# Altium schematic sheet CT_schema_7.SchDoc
size 251 x 159 mm
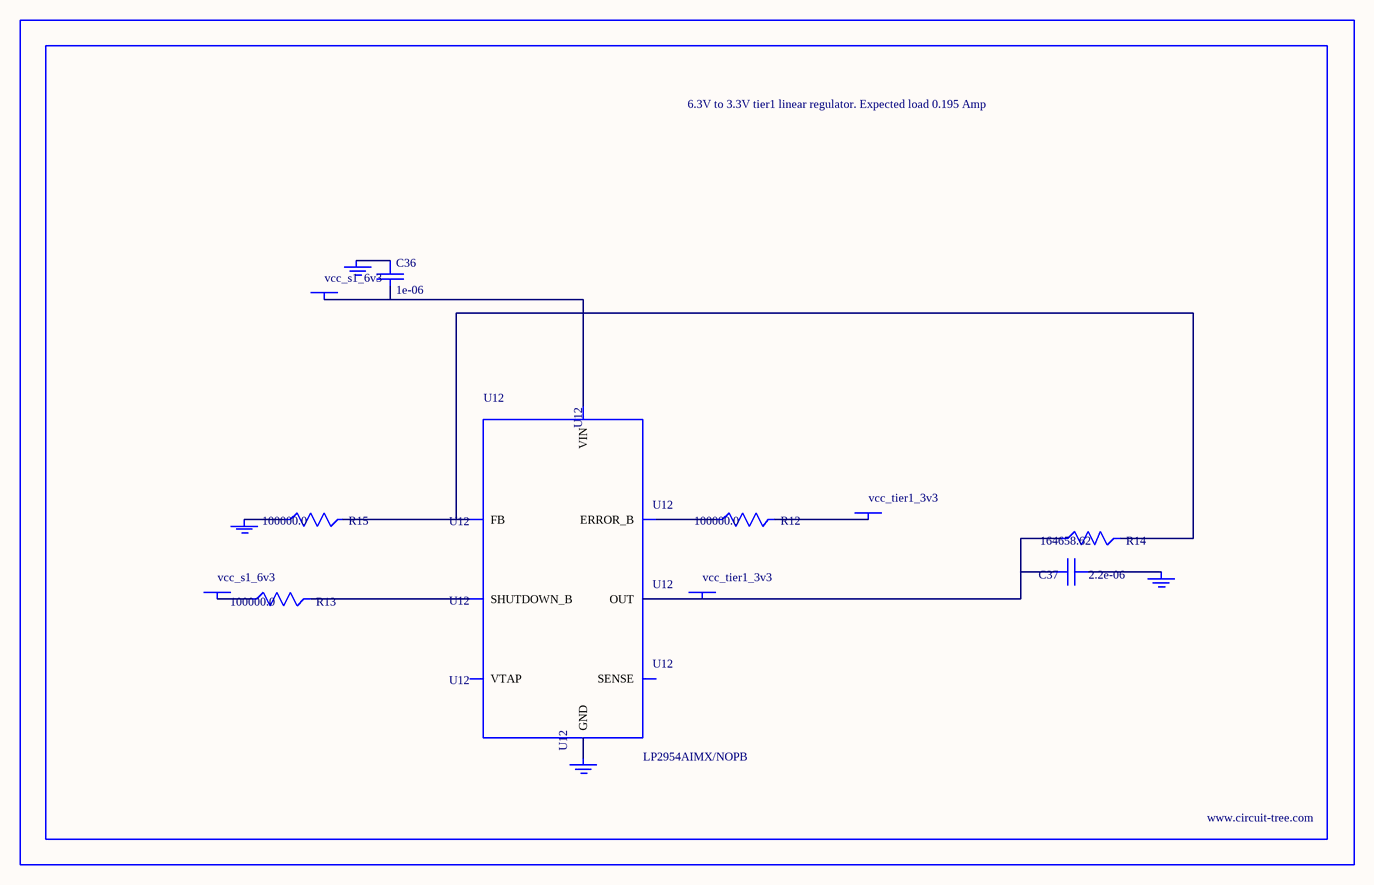
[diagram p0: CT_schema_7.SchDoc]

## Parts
BORDER6  (no value)
C36  1e-06  [EXV-9B]
C37  2.2e-06  [EXV-9B]
GND_INSTANCE_6_0  (no value)
GND_INSTANCE_6_1  (no value)
GND_INSTANCE_6_2  (no value)
GND_INSTANCE_6_3  (no value)
POWER_INSTANCE_6_0  vcc_s1_6v3
POWER_INSTANCE_6_1  vcc_tier1_3v3
POWER_INSTANCE_6_2  vcc_s1_6v3
POWER_INSTANCE_6_3  vcc_tier1_3v3
R12  100000.0  [R0603]
R13  100000.0  [R0603]
R14  164658.62  [R0603]
R15  100000.0  [R0603]
U12  LP2954AIMX/NOPB  [LP2954]

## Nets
NetC36_1: C36.1 GND_INSTANCE_6_2.0(GND)
NetC36_2: C36.2 POWER_INSTANCE_6_2.0(PWR) U12.8(VIN)
NetC37_1: C37.1 GND_INSTANCE_6_0.0(GND)
NetC37_2: C37.2 POWER_INSTANCE_6_3.0(PWR) R14.1 U12.1(OUT)
NetGND_INSTANCE_6_1_0: GND_INSTANCE_6_1.0(GND) R15.1
NetGND_INSTANCE_6_3_0: GND_INSTANCE_6_3.0(GND) U12.4(GND)
NetPOWER_INSTANCE_6_0_0: POWER_INSTANCE_6_0.0(PWR) R13.1
NetPOWER_INSTANCE_6_1_0: POWER_INSTANCE_6_1.0(PWR) R12.2
NetR12_1: R12.1 U12.5(ERROR_B)
NetR13_2: R13.2 U12.3(SHUTDOWN_B)
NetR14_2: R14.2 R15.2 U12.7(FB)

Not connected (* = marked no-connect by the designer): U12 2(SENSE) 6(VTAP)

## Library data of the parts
BORDER6 = BORDER_PAGE6
C36 = EDK105M050A9BAA
C37 = EDK225M050A9BAA
GND_INSTANCE_6_0-GND_INSTANCE_6_3 = GND
POWER_INSTANCE_6_0-POWER_INSTANCE_6_3 = PWR
R12 R13 R15 = RC0603JR-07100KL
R14 = R14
